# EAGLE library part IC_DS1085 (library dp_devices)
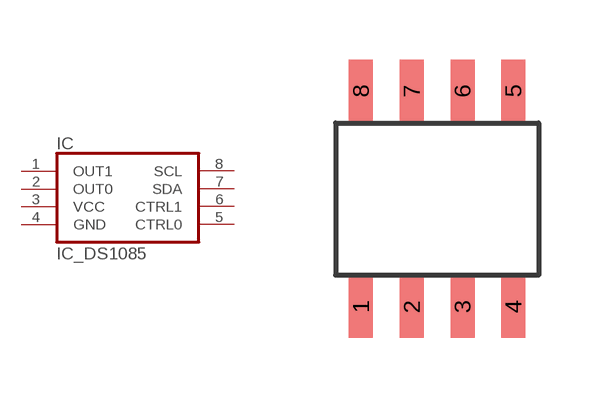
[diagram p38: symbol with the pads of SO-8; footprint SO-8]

Designator prefix IC

## IC_DS1085-SO-8  [SO-8]
1  OUT1  out
2  OUT0  out
3  VCC  pwr
4  GND  pwr
5  CTRL0  in
6  CTRL1  in
7  SDA
8  SCL  in

## Footprint SO-8 (pad centres in mm)
smd 0.6 x 1.55: 1 -1.905,-2.69; 2 -0.635,-2.69; 3 0.635,-2.69; 4 1.905,-2.69; 5 1.905,2.71; 6 0.635,2.71; 7 -0.635,2.71; 8 -1.905,2.71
